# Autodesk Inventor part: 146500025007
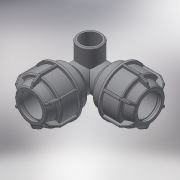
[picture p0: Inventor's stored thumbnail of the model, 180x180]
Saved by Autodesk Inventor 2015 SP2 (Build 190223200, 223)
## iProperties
Created: 2017-08
Part Number: 146500025007
Material: Generic
Description: PLASSON L.14 CORNER TEE ELBOW FEMALE (SILVER) 25-3/4"-25
Document SubType Name: Modeling
Designer: KIM
Density: 1 g/cm^3
Appearance: Default
Author: KIM
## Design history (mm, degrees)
derived "146500.ipt"
feature "Solid1::146500.ipt"
feature "Solid2::146500.ipt"
feature "Solid3::146500.ipt"
tag "TaggingFeature1"
body "Solid1"
body "Solid2"
body "Solid3"
other parameters: "d1" = 25, "d2" = 44, "d4" = 15 deg, "d5" = 29.04, "d6" = 9.5832, "d16" = 25.5, "d17" = 2.2, "d24" = 2.2, "d25" = 45, "d26" = 37.5, "d27" = 2.2, "d28" = 135 deg, "d29" = 1.32, "d31" = 1.25, "d46" = 150 deg, "d49" = 2.5, "d50" = 0, "d58" = 0.75, "d61" = 360 deg, "d63" = 22.91115, "d95" = 24.117, "d96" = 31.3521, "d97" = 17, "d98" = 18.08775, "d108" = 1.25, "d113" = 62, "d114" = 44.88, "d115" = 36.1755, "d116" = 45 deg, "d120" = 90 deg, "d123" = 0, "d124" = 0, "d125" = 5.78808, "d129" = 0, "d131" = 0, "d132" = 0, "d133" = 0, "d_" = 25, "G_" = 24.117, "A_" = 62, "l_" = 44, "l_2" = 17
